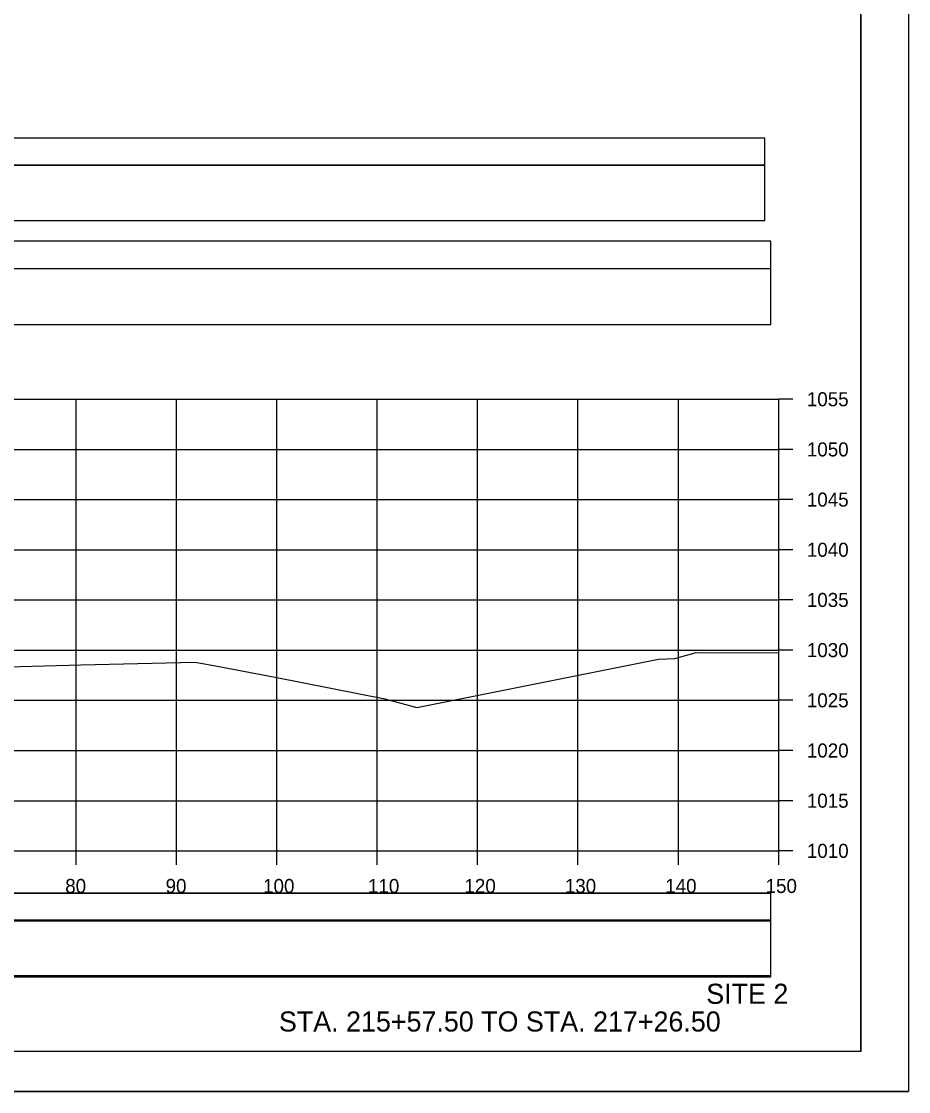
# Model space of a CAD drawing. Extents: x 1370565 to 1374448, y 301010 to 304637.
# Drawn here: x 1373443.4 to 1373531.7, y 302578.3 to 302685 of the extents above; entities that cross this region are included whole.
import ezdxf

# ---------------------------------------------------------------- set-up
doc = ezdxf.new("R2010")
doc.units = 0
for name, color, linetype in [('Default', 7, 'Continuous'), ('R_Axis', 7, 'Continuous'), ('R_Axis Annot', 7, 'Continuous'), ('R_Border', 7, 'Continuous'), ('R_Draft', 7, 'Continuous'), ('R_Drive', 7, 'Continuous'), ('R_Exist Surface', 7, 'Continuous'), ('R_Grid', 7, 'Continuous'), ('R_No Plot', 7, 'Continuous')]:
    doc.layers.add(name, color=color, linetype=linetype)

msp = doc.modelspace()

# ---------------------------------------------------------------- linework, layer by layer
at = {"layer": 'Default'}
for points in [[(1373219.61, 302660.37), (1373518.02, 302660.37), (1373518.02, 302663.07), (1373219.61, 302663.07)], [(1373219.61, 302654.79), (1373518.02, 302654.79), (1373518.02, 302660.31), (1373219.61, 302660.31)], [(1373219.61, 302595.37), (1373518.02, 302595.37), (1373518.02, 302598.07), (1373219.61, 302598.07)], [(1373219.61, 302589.79), (1373518.02, 302589.79), (1373518.02, 302595.31), (1373219.61, 302595.31)]]:
    msp.add_lwpolyline(points, close=True, dxfattribs=at)
at = {"layer": 'R_Axis'}
for p, q in [((1373518.81, 302602.33), (1373518.81, 302647.33)), ((1373520.21, 302647.33), (1373518.81, 302647.33)), ((1373520.21, 302642.33), (1373518.81, 302642.33)), ((1373520.21, 302637.33), (1373518.81, 302637.33)), ((1373520.21, 302632.33), (1373518.81, 302632.33)), ((1373520.21, 302627.33), (1373518.81, 302627.33)), ((1373520.21, 302622.33), (1373518.81, 302622.33)), ((1373520.21, 302617.33), (1373518.81, 302617.33)), ((1373520.21, 302612.33), (1373518.81, 302612.33)), ((1373520.21, 302607.33), (1373518.81, 302607.33)), ((1373218.81, 302602.33), (1373518.81, 302602.33)), ((1373448.81, 302600.93), (1373448.81, 302602.33)), ((1373458.81, 302600.93), (1373458.81, 302602.33)), ((1373468.81, 302600.93), (1373468.81, 302602.33)), ((1373478.81, 302600.93), (1373478.81, 302602.33)), ((1373488.81, 302600.93), (1373488.81, 302602.33)), ((1373498.81, 302600.93), (1373498.81, 302602.33)), ((1373508.81, 302600.93), (1373508.81, 302602.33)), ((1373518.81, 302600.93), (1373518.81, 302602.33)), ((1373520.21, 302602.33), (1373518.81, 302602.33))]:
    msp.add_line(p, q, dxfattribs=at)
at = {"layer": 'R_Border'}
for q in [(1373526.99, 302787.79), (1373210.81, 302582.33)]:
    msp.add_line((1373526.99, 302582.33), q, dxfattribs=at)
at = {"layer": 'R_Drive'}
for points in [[(1373219.02, 302670.65), (1373517.44, 302670.65), (1373517.44, 302673.35), (1373219.02, 302673.35)], [(1373219.02, 302665.13), (1373517.44, 302665.13), (1373517.44, 302670.65), (1373219.02, 302670.65)], [(1373219.61, 302595.42), (1373518.02, 302595.42), (1373518.02, 302598.13), (1373219.61, 302598.13)], [(1373219.61, 302589.9), (1373518.02, 302589.9), (1373518.02, 302595.42), (1373219.61, 302595.42)]]:
    msp.add_lwpolyline(points, close=True, dxfattribs=at)
at = {"layer": 'R_Exist Surface'}
msp.add_lwpolyline([(1373440.79, 302620.64), (1373449.29, 302620.86), (1373460.63, 302621.13), (1373462.17, 302620.87), (1373468.65, 302619.64), (1373479.58, 302617.49), (1373482.77, 302616.61), (1373506.84, 302621.44), (1373508.45, 302621.48), (1373510.57, 302622.09), (1373512.82, 302622.06), (1373518.81, 302622.09)], dxfattribs=at)
at = {"layer": 'R_Grid'}
for p, q in [((1373218.81, 302647.33), (1373518.81, 302647.33)), ((1373448.81, 302602.33), (1373448.81, 302647.33)), ((1373458.81, 302602.33), (1373458.81, 302647.33)), ((1373468.81, 302602.33), (1373468.81, 302647.33)), ((1373478.81, 302602.33), (1373478.81, 302647.33)), ((1373488.81, 302602.33), (1373488.81, 302647.33)), ((1373498.81, 302602.33), (1373498.81, 302647.33)), ((1373508.81, 302602.33), (1373508.81, 302647.33)), ((1373518.81, 302602.33), (1373518.81, 302647.33)), ((1373218.81, 302642.33), (1373518.81, 302642.33)), ((1373218.81, 302637.33), (1373518.81, 302637.33)), ((1373218.81, 302632.33), (1373518.81, 302632.33)), ((1373218.81, 302627.33), (1373518.81, 302627.33)), ((1373218.81, 302622.33), (1373518.81, 302622.33)), ((1373218.81, 302617.33), (1373518.81, 302617.33)), ((1373218.81, 302612.33), (1373518.81, 302612.33)), ((1373218.81, 302607.33), (1373518.81, 302607.33)), ((1373218.81, 302602.33), (1373518.81, 302602.33))]:
    msp.add_line(p, q, dxfattribs=at)
at = {"layer": 'R_No Plot'}
msp.add_line((1373198.41, 302578.35), (1373531.75, 302578.35), dxfattribs=at)
for points in [[(1373198.41, 302791.68), (1373531.75, 302791.68), (1373531.75, 302578.34), (1373198.41, 302578.34)], [(1373444.73, 302787.79), (1373464.35, 302787.79), (1373464.35, 302777.91), (1373480.47, 302777.91), (1373503.67, 302777.91), (1373503.67, 302753.57), (1373526.99, 302753.57), (1373526.99, 302582.33), (1373210.81, 302582.33), (1373210.81, 302787.79)]]:
    msp.add_lwpolyline(points, close=True, dxfattribs=at)

# ---------------------------------------------------------------- texts
at = {"layer": 'R_Axis Annot'}
for s, p in [('1055', (1373521.61, 302646.63)), ('1050', (1373521.61, 302641.63)), ('1045', (1373521.61, 302636.63)), ('1040', (1373521.61, 302631.63)), ('1035', (1373521.61, 302626.63)), ('1030', (1373521.61, 302621.63)), ('1025', (1373521.61, 302616.63)), ('1020', (1373521.61, 302611.63)), ('1015', (1373521.61, 302606.63)), ('1010', (1373521.61, 302601.63)), ('80', (1373447.73, 302598.13)), ('90', (1373457.73, 302598.13)), ('100', (1373467.44, 302598.13)), ('110', (1373477.89, 302598.13)), ('120', (1373487.5, 302598.13)), ('130', (1373497.5, 302598.13)), ('140', (1373507.5, 302598.13)), ('150', (1373517.5, 302598.13))]:
    msp.add_text(s, height=1.4, dxfattribs=at).set_placement(p)
at = {"layer": 'R_Draft'}
for s, p in [('SITE 2', (1373511.59, 302587.09)), ('STA. 215+57.50 TO STA. 217+26.50', (1373469.02, 302584.33))]:
    msp.add_text(s, height=2, dxfattribs=at).set_placement(p)

doc.saveas('drawing.dxf')
